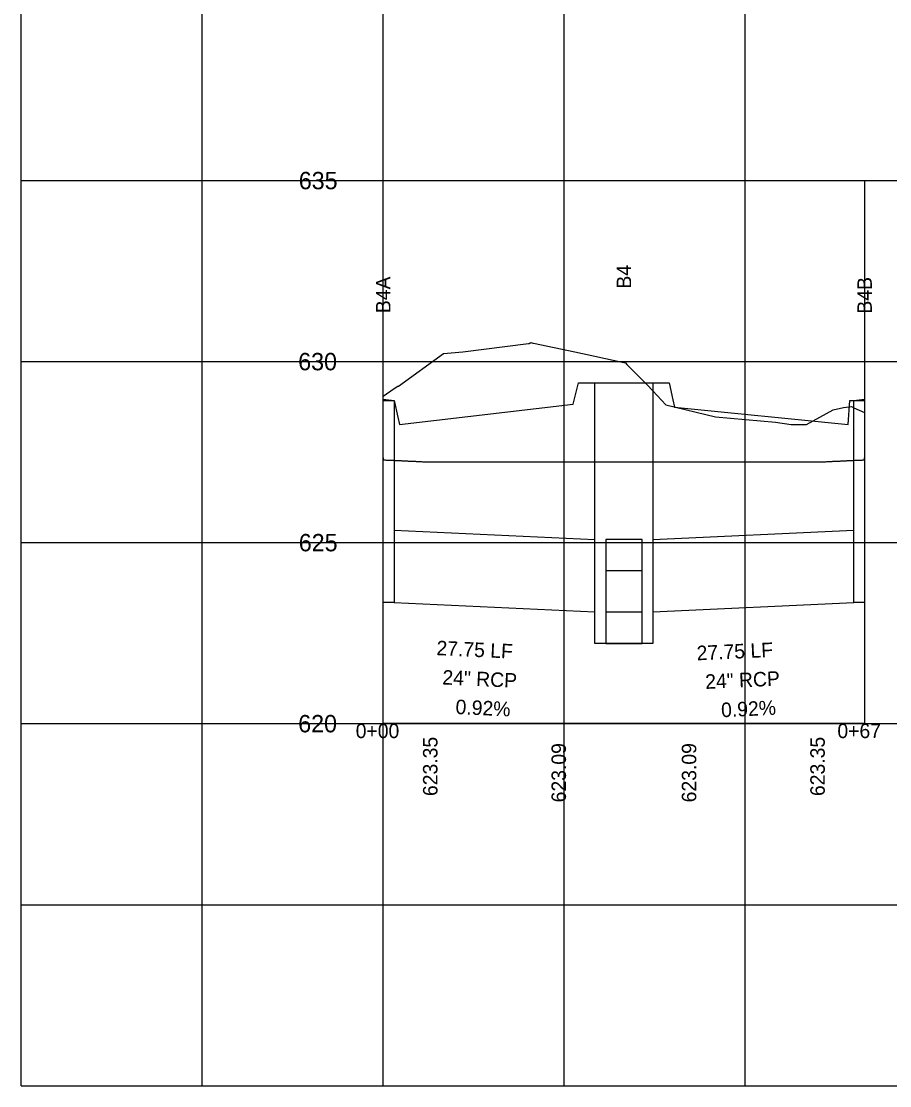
# Model space of a CAD drawing. Extents: x 2254979 to 2278074, y 13790855 to 13792793.
# Drawn here: x 2276749.4 to 2276869.4, y 13792492.6 to 13792639.6 of the extents above; entities that cross this region are included whole.
import ezdxf

# ---------------------------------------------------------------- set-up
doc = ezdxf.new("R2010")
doc.units = 0
for name, color, linetype in [('blank4', 7, 'Continuous'), ('BORD_grid_bottom_major_5int', 7, 'Continuous'), ('D_DRN_PROF_HGL', 7, 'Continuous'), ('D_PROF_1', 7, 'Continuous'), ('D_PROF_NOTES_1', 7, 'Continuous'), ('Default', 7, 'Continuous'), ('Drain_PipeInside', 7, 'Continuous'), ('E_Terrain', 7, 'Continuous'), ('Inlet', 7, 'Continuous'), ('z - Construction', 7, 'Continuous')]:
    doc.layers.add(name, color=color, linetype=linetype)

msp = doc.modelspace()

# ---------------------------------------------------------------- linework, layer by layer
at = {"layer": 'blank4'}
msp.add_lwpolyline([(2276799.4, 13792542.6), (2276799.4, 13792617.6), (2276865.9, 13792617.6), (2276865.9, 13792542.6)], close=True, dxfattribs=at)
at = {"layer": 'BORD_grid_bottom_major_5int'}
for p, q in [((2276749.4, 13792492.6), (2276749.4, 13792792.6)), ((2276774.4, 13792492.6), (2276774.4, 13792792.6)), ((2276799.4, 13792492.6), (2276799.4, 13792792.6)), ((2276824.4, 13792492.6), (2276824.4, 13792792.6)), ((2276849.4, 13792492.6), (2276849.4, 13792792.6)), ((2276749.4, 13792617.6), (2277074.4, 13792617.6)), ((2276749.4, 13792592.6), (2277074.4, 13792592.6)), ((2276749.4, 13792567.6), (2277074.4, 13792567.6)), ((2276749.4, 13792542.6), (2277074.4, 13792542.6)), ((2276749.4, 13792517.6), (2277074.4, 13792517.6)), ((2276749.4, 13792492.6), (2277074.4, 13792492.6))]:
    msp.add_line(p, q, dxfattribs=at)
at = {"layer": 'D_DRN_PROF_HGL'}
msp.add_line((2276832.65, 13792578.77), (2276832.65, 13792578.77), dxfattribs=at)
for points in [[(2276799.4, 13792579.32), (2276799.4, 13792579.03), (2276799.47, 13792579.03), (2276799.58, 13792579.02), (2276799.69, 13792579.02), (2276799.8, 13792579.01), (2276799.91, 13792579.01), (2276800.01, 13792579), (2276800.12, 13792579), (2276800.23, 13792578.99), (2276800.34, 13792578.99), (2276800.45, 13792578.98), (2276800.56, 13792578.98), (2276800.67, 13792578.97), (2276800.78, 13792578.97), (2276800.89, 13792578.96), (2276801, 13792578.96), (2276801.11, 13792578.95), (2276801.22, 13792578.95), (2276801.32, 13792578.94), (2276801.43, 13792578.94), (2276801.54, 13792578.93), (2276801.65, 13792578.93), (2276801.76, 13792578.92), (2276801.87, 13792578.92), (2276801.98, 13792578.91), (2276802.09, 13792578.91), (2276802.2, 13792578.9), (2276802.31, 13792578.9), (2276802.42, 13792578.89), (2276802.53, 13792578.89), (2276802.63, 13792578.88), (2276802.74, 13792578.88), (2276802.85, 13792578.87), (2276802.96, 13792578.87), (2276803.07, 13792578.86), (2276803.18, 13792578.86), (2276803.29, 13792578.85), (2276803.4, 13792578.85), (2276803.51, 13792578.84), (2276803.62, 13792578.84), (2276803.73, 13792578.83), (2276803.84, 13792578.83), (2276803.94, 13792578.82), (2276804.05, 13792578.82), (2276804.16, 13792578.81), (2276804.27, 13792578.81), (2276804.38, 13792578.8), (2276804.49, 13792578.8), (2276804.6, 13792578.79), (2276804.71, 13792578.79), (2276804.82, 13792578.78), (2276804.93, 13792578.78), (2276805.04, 13792578.78), (2276805.15, 13792578.78), (2276805.25, 13792578.78), (2276805.36, 13792578.78), (2276805.47, 13792578.78), (2276805.58, 13792578.78), (2276805.69, 13792578.78), (2276805.8, 13792578.78), (2276805.91, 13792578.78), (2276806.02, 13792578.78), (2276806.13, 13792578.78), (2276806.24, 13792578.78), (2276806.35, 13792578.78), (2276806.46, 13792578.78), (2276806.56, 13792578.78), (2276806.67, 13792578.78), (2276806.78, 13792578.78), (2276806.89, 13792578.78), (2276807, 13792578.78), (2276807.11, 13792578.78), (2276807.22, 13792578.77), (2276807.33, 13792578.77), (2276807.44, 13792578.77), (2276807.55, 13792578.77), (2276807.66, 13792578.77), (2276807.77, 13792578.77), (2276807.87, 13792578.77), (2276807.98, 13792578.77), (2276808.09, 13792578.77), (2276808.2, 13792578.77), (2276808.31, 13792578.77), (2276808.42, 13792578.77), (2276808.53, 13792578.77), (2276808.64, 13792578.77), (2276808.75, 13792578.77), (2276808.86, 13792578.77), (2276808.97, 13792578.77), (2276809.08, 13792578.77), (2276809.18, 13792578.77), (2276809.29, 13792578.77), (2276809.4, 13792578.77), (2276809.51, 13792578.77), (2276809.62, 13792578.77), (2276809.73, 13792578.77), (2276809.84, 13792578.77), (2276809.95, 13792578.77), (2276810.06, 13792578.77), (2276810.17, 13792578.77), (2276810.28, 13792578.77), (2276810.39, 13792578.77), (2276810.49, 13792578.77), (2276810.6, 13792578.77), (2276810.71, 13792578.77), (2276810.82, 13792578.77), (2276810.93, 13792578.77), (2276811.04, 13792578.77), (2276811.15, 13792578.77), (2276811.26, 13792578.77), (2276811.37, 13792578.77), (2276811.48, 13792578.77), (2276811.59, 13792578.77), (2276811.7, 13792578.77), (2276811.8, 13792578.77), (2276811.91, 13792578.77), (2276812.02, 13792578.77), (2276812.13, 13792578.77), (2276812.24, 13792578.77), (2276812.35, 13792578.77), (2276812.46, 13792578.77), (2276812.57, 13792578.77), (2276812.68, 13792578.77), (2276812.79, 13792578.77), (2276812.9, 13792578.77), (2276813, 13792578.77), (2276813.11, 13792578.77), (2276813.22, 13792578.77), (2276813.33, 13792578.77), (2276813.44, 13792578.77), (2276813.55, 13792578.77), (2276813.66, 13792578.77), (2276813.77, 13792578.77), (2276813.88, 13792578.77), (2276813.99, 13792578.77), (2276814.1, 13792578.77), (2276814.21, 13792578.77), (2276814.31, 13792578.77), (2276814.42, 13792578.77), (2276814.53, 13792578.77), (2276814.64, 13792578.77), (2276814.75, 13792578.77), (2276814.86, 13792578.77), (2276814.97, 13792578.77), (2276815.08, 13792578.77), (2276815.19, 13792578.77), (2276815.3, 13792578.77), (2276815.41, 13792578.77), (2276815.52, 13792578.77), (2276815.62, 13792578.77), (2276815.73, 13792578.77), (2276815.84, 13792578.77), (2276815.95, 13792578.77), (2276816.06, 13792578.77), (2276816.17, 13792578.77), (2276816.28, 13792578.77), (2276816.39, 13792578.77), (2276816.5, 13792578.77), (2276816.61, 13792578.77), (2276816.72, 13792578.77), (2276816.83, 13792578.77), (2276816.93, 13792578.77), (2276817.04, 13792578.77), (2276817.15, 13792578.77), (2276817.26, 13792578.77), (2276817.37, 13792578.77), (2276817.48, 13792578.77), (2276817.59, 13792578.77), (2276817.7, 13792578.77), (2276817.81, 13792578.77), (2276817.92, 13792578.77), (2276818.03, 13792578.77), (2276818.14, 13792578.77), (2276818.24, 13792578.77), (2276818.35, 13792578.77), (2276818.46, 13792578.77), (2276818.57, 13792578.77), (2276818.68, 13792578.77), (2276818.79, 13792578.77), (2276818.9, 13792578.77), (2276819.01, 13792578.77), (2276819.12, 13792578.77), (2276819.23, 13792578.77), (2276819.34, 13792578.77), (2276819.45, 13792578.77), (2276819.55, 13792578.77), (2276819.66, 13792578.77), (2276819.77, 13792578.77), (2276819.88, 13792578.77), (2276819.99, 13792578.77), (2276820.1, 13792578.77), (2276820.21, 13792578.77), (2276820.32, 13792578.77), (2276820.43, 13792578.77), (2276820.54, 13792578.77), (2276820.65, 13792578.77), (2276820.76, 13792578.77), (2276820.86, 13792578.77), (2276820.97, 13792578.77), (2276821.08, 13792578.77), (2276821.19, 13792578.77), (2276821.3, 13792578.77), (2276821.41, 13792578.77), (2276821.52, 13792578.77), (2276821.63, 13792578.77), (2276821.74, 13792578.77), (2276821.85, 13792578.77), (2276821.96, 13792578.77), (2276822.07, 13792578.77), (2276822.17, 13792578.77), (2276822.28, 13792578.77), (2276822.39, 13792578.77), (2276822.5, 13792578.77), (2276822.61, 13792578.77), (2276822.72, 13792578.77), (2276822.83, 13792578.77), (2276822.94, 13792578.77), (2276823.05, 13792578.77), (2276823.16, 13792578.77), (2276823.27, 13792578.77), (2276823.38, 13792578.77), (2276823.48, 13792578.77), (2276823.59, 13792578.77), (2276823.7, 13792578.77), (2276823.81, 13792578.77), (2276823.92, 13792578.77), (2276824.03, 13792578.77), (2276824.14, 13792578.77), (2276824.25, 13792578.77), (2276824.36, 13792578.77), (2276824.47, 13792578.77), (2276824.58, 13792578.77), (2276824.69, 13792578.77), (2276824.79, 13792578.77), (2276824.9, 13792578.77), (2276825.01, 13792578.77), (2276825.12, 13792578.77), (2276825.23, 13792578.77), (2276825.34, 13792578.77), (2276825.45, 13792578.77), (2276825.56, 13792578.77), (2276825.67, 13792578.77), (2276825.78, 13792578.77), (2276825.89, 13792578.77), (2276826, 13792578.77), (2276826.1, 13792578.77), (2276826.21, 13792578.77), (2276826.32, 13792578.77), (2276826.43, 13792578.77), (2276826.54, 13792578.77), (2276826.65, 13792578.77), (2276826.76, 13792578.77), (2276826.87, 13792578.77), (2276826.98, 13792578.77), (2276827.09, 13792578.77), (2276827.2, 13792578.77), (2276827.31, 13792578.77), (2276827.41, 13792578.77), (2276827.52, 13792578.77), (2276827.63, 13792578.77), (2276827.74, 13792578.77), (2276827.85, 13792578.77), (2276827.96, 13792578.77), (2276828.07, 13792578.77), (2276828.18, 13792578.77), (2276828.29, 13792578.77), (2276828.4, 13792578.77), (2276828.51, 13792578.77), (2276828.62, 13792578.77), (2276828.72, 13792578.77), (2276828.83, 13792578.77), (2276828.94, 13792578.77), (2276829.05, 13792578.77), (2276829.16, 13792578.77), (2276829.27, 13792578.77), (2276829.38, 13792578.77), (2276829.49, 13792578.77), (2276829.6, 13792578.77), (2276829.71, 13792578.77), (2276829.82, 13792578.77), (2276829.93, 13792578.77), (2276830.03, 13792578.77), (2276830.14, 13792578.77), (2276830.25, 13792578.77), (2276830.36, 13792578.77), (2276830.47, 13792578.77), (2276830.58, 13792578.77), (2276830.69, 13792578.77), (2276830.8, 13792578.77), (2276830.91, 13792578.77), (2276831.02, 13792578.77), (2276831.13, 13792578.77), (2276831.24, 13792578.77), (2276831.34, 13792578.77), (2276831.45, 13792578.77), (2276831.56, 13792578.77), (2276831.67, 13792578.77), (2276831.78, 13792578.77), (2276831.89, 13792578.77), (2276832, 13792578.77), (2276832.11, 13792578.77), (2276832.22, 13792578.77), (2276832.33, 13792578.77), (2276832.44, 13792578.77), (2276832.55, 13792578.77), (2276832.65, 13792578.77)], [(2276832.65, 13792578.77), (2276832.76, 13792578.77), (2276832.87, 13792578.77), (2276832.98, 13792578.77), (2276833.09, 13792578.77), (2276833.2, 13792578.77), (2276833.31, 13792578.77), (2276833.42, 13792578.77), (2276833.53, 13792578.77), (2276833.63, 13792578.77), (2276833.74, 13792578.77), (2276833.85, 13792578.77), (2276833.96, 13792578.77), (2276834.07, 13792578.77), (2276834.18, 13792578.77), (2276834.29, 13792578.77), (2276834.4, 13792578.77), (2276834.51, 13792578.77), (2276834.62, 13792578.77), (2276834.72, 13792578.77), (2276834.83, 13792578.77), (2276834.94, 13792578.77), (2276835.05, 13792578.77), (2276835.16, 13792578.77), (2276835.27, 13792578.77), (2276835.38, 13792578.77), (2276835.49, 13792578.77), (2276835.6, 13792578.77), (2276835.71, 13792578.77), (2276835.81, 13792578.77), (2276835.92, 13792578.77), (2276836.03, 13792578.77), (2276836.14, 13792578.77), (2276836.25, 13792578.77), (2276836.36, 13792578.77), (2276836.47, 13792578.77), (2276836.58, 13792578.77), (2276836.69, 13792578.77), (2276836.79, 13792578.77), (2276836.9, 13792578.77), (2276837.01, 13792578.77), (2276837.12, 13792578.77), (2276837.23, 13792578.77), (2276837.34, 13792578.77), (2276837.45, 13792578.77), (2276837.56, 13792578.77), (2276837.67, 13792578.77), (2276837.78, 13792578.77), (2276837.88, 13792578.77), (2276837.99, 13792578.77), (2276838.1, 13792578.77), (2276838.21, 13792578.77), (2276838.32, 13792578.77), (2276838.43, 13792578.77), (2276838.54, 13792578.77), (2276838.65, 13792578.77), (2276838.76, 13792578.77), (2276838.86, 13792578.77), (2276838.97, 13792578.77), (2276839.08, 13792578.77), (2276839.19, 13792578.77), (2276839.3, 13792578.77), (2276839.41, 13792578.77), (2276839.52, 13792578.77), (2276839.63, 13792578.77), (2276839.74, 13792578.77), (2276839.85, 13792578.77), (2276839.95, 13792578.77), (2276840.06, 13792578.77), (2276840.17, 13792578.77), (2276840.28, 13792578.77), (2276840.39, 13792578.77), (2276840.5, 13792578.77), (2276840.61, 13792578.77), (2276840.72, 13792578.77), (2276840.83, 13792578.77), (2276840.93, 13792578.77), (2276841.04, 13792578.77), (2276841.15, 13792578.77), (2276841.26, 13792578.77), (2276841.37, 13792578.77), (2276841.48, 13792578.77), (2276841.59, 13792578.77), (2276841.7, 13792578.77), (2276841.81, 13792578.77), (2276841.92, 13792578.77), (2276842.02, 13792578.77), (2276842.13, 13792578.77), (2276842.24, 13792578.77), (2276842.35, 13792578.77), (2276842.46, 13792578.77), (2276842.57, 13792578.77), (2276842.68, 13792578.77), (2276842.79, 13792578.77), (2276842.9, 13792578.77), (2276843.01, 13792578.77), (2276843.11, 13792578.77), (2276843.22, 13792578.77), (2276843.33, 13792578.77), (2276843.44, 13792578.77), (2276843.55, 13792578.77), (2276843.66, 13792578.77), (2276843.77, 13792578.77), (2276843.88, 13792578.77), (2276843.99, 13792578.77), (2276844.09, 13792578.77), (2276844.2, 13792578.77), (2276844.31, 13792578.77), (2276844.42, 13792578.77), (2276844.53, 13792578.77), (2276844.64, 13792578.77), (2276844.75, 13792578.77), (2276844.86, 13792578.77), (2276844.97, 13792578.77), (2276845.08, 13792578.77), (2276845.18, 13792578.77), (2276845.29, 13792578.77), (2276845.4, 13792578.77), (2276845.51, 13792578.77), (2276845.62, 13792578.77), (2276845.73, 13792578.77), (2276845.84, 13792578.77), (2276845.95, 13792578.77), (2276846.06, 13792578.77), (2276846.16, 13792578.77), (2276846.27, 13792578.77), (2276846.38, 13792578.77), (2276846.49, 13792578.77), (2276846.6, 13792578.77), (2276846.71, 13792578.77), (2276846.82, 13792578.77), (2276846.93, 13792578.77), (2276847.04, 13792578.77), (2276847.15, 13792578.77), (2276847.25, 13792578.77), (2276847.36, 13792578.77), (2276847.47, 13792578.77), (2276847.58, 13792578.77), (2276847.69, 13792578.77), (2276847.8, 13792578.77), (2276847.91, 13792578.77), (2276848.02, 13792578.77), (2276848.13, 13792578.77), (2276848.23, 13792578.77), (2276848.34, 13792578.77), (2276848.45, 13792578.77), (2276848.56, 13792578.77), (2276848.67, 13792578.77), (2276848.78, 13792578.77), (2276848.89, 13792578.77), (2276849, 13792578.77), (2276849.11, 13792578.77), (2276849.22, 13792578.77), (2276849.32, 13792578.77), (2276849.43, 13792578.77), (2276849.54, 13792578.77), (2276849.65, 13792578.77), (2276849.76, 13792578.77), (2276849.87, 13792578.77), (2276849.98, 13792578.77), (2276850.09, 13792578.77), (2276850.2, 13792578.77), (2276850.31, 13792578.77), (2276850.41, 13792578.77), (2276850.52, 13792578.77), (2276850.63, 13792578.77), (2276850.74, 13792578.77), (2276850.85, 13792578.77), (2276850.96, 13792578.77), (2276851.07, 13792578.77), (2276851.18, 13792578.77), (2276851.29, 13792578.77), (2276851.39, 13792578.77), (2276851.5, 13792578.77), (2276851.61, 13792578.77), (2276851.72, 13792578.77), (2276851.83, 13792578.77), (2276851.94, 13792578.77), (2276852.05, 13792578.77), (2276852.16, 13792578.77), (2276852.27, 13792578.77), (2276852.38, 13792578.77), (2276852.48, 13792578.77), (2276852.59, 13792578.77), (2276852.7, 13792578.77), (2276852.81, 13792578.77), (2276852.92, 13792578.77), (2276853.03, 13792578.77), (2276853.14, 13792578.77), (2276853.25, 13792578.77), (2276853.36, 13792578.77), (2276853.46, 13792578.77), (2276853.57, 13792578.77), (2276853.68, 13792578.77), (2276853.79, 13792578.77), (2276853.9, 13792578.77), (2276854.01, 13792578.77), (2276854.12, 13792578.77), (2276854.23, 13792578.77), (2276854.34, 13792578.77), (2276854.45, 13792578.77), (2276854.55, 13792578.77), (2276854.66, 13792578.77), (2276854.77, 13792578.77), (2276854.88, 13792578.77), (2276854.99, 13792578.77), (2276855.1, 13792578.77), (2276855.21, 13792578.77), (2276855.32, 13792578.77), (2276855.43, 13792578.77), (2276855.53, 13792578.77), (2276855.64, 13792578.77), (2276855.75, 13792578.77), (2276855.86, 13792578.77), (2276855.97, 13792578.77), (2276856.08, 13792578.77), (2276856.19, 13792578.77), (2276856.3, 13792578.77), (2276856.41, 13792578.77), (2276856.52, 13792578.77), (2276856.62, 13792578.77), (2276856.73, 13792578.77), (2276856.84, 13792578.77), (2276856.95, 13792578.77), (2276857.06, 13792578.77), (2276857.17, 13792578.77), (2276857.28, 13792578.77), (2276857.39, 13792578.77), (2276857.5, 13792578.77), (2276857.61, 13792578.77), (2276857.71, 13792578.77), (2276857.82, 13792578.77), (2276857.93, 13792578.77), (2276858.04, 13792578.77), (2276858.15, 13792578.77), (2276858.26, 13792578.77), (2276858.37, 13792578.77), (2276858.48, 13792578.77), (2276858.59, 13792578.77), (2276858.69, 13792578.77), (2276858.8, 13792578.77), (2276858.91, 13792578.77), (2276859.02, 13792578.77), (2276859.13, 13792578.77), (2276859.24, 13792578.77), (2276859.35, 13792578.77), (2276859.46, 13792578.77), (2276859.57, 13792578.77), (2276859.68, 13792578.77), (2276859.78, 13792578.77), (2276859.89, 13792578.77), (2276860, 13792578.77), (2276860.11, 13792578.77), (2276860.22, 13792578.77), (2276860.33, 13792578.77), (2276860.44, 13792578.77), (2276860.55, 13792578.78), (2276860.66, 13792578.79), (2276860.76, 13792578.79), (2276860.87, 13792578.8), (2276860.98, 13792578.8), (2276861.09, 13792578.81), (2276861.2, 13792578.81), (2276861.31, 13792578.82), (2276861.42, 13792578.82), (2276861.53, 13792578.83), (2276861.64, 13792578.83), (2276861.75, 13792578.84), (2276861.85, 13792578.84), (2276861.96, 13792578.85), (2276862.07, 13792578.85), (2276862.18, 13792578.86), (2276862.29, 13792578.86), (2276862.4, 13792578.87), (2276862.51, 13792578.87), (2276862.62, 13792578.88), (2276862.73, 13792578.88), (2276862.83, 13792578.89), (2276862.94, 13792578.89), (2276863.05, 13792578.9), (2276863.16, 13792578.9), (2276863.27, 13792578.91), (2276863.38, 13792578.91), (2276863.49, 13792578.92), (2276863.6, 13792578.92), (2276863.71, 13792578.93), (2276863.82, 13792578.93), (2276863.92, 13792578.94), (2276864.03, 13792578.94), (2276864.14, 13792578.95), (2276864.25, 13792578.95), (2276864.36, 13792578.96), (2276864.47, 13792578.96), (2276864.58, 13792578.97), (2276864.69, 13792578.97), (2276864.8, 13792578.98), (2276864.91, 13792578.98), (2276865.01, 13792578.99), (2276865.12, 13792578.99), (2276865.23, 13792579), (2276865.34, 13792579), (2276865.45, 13792579.01), (2276865.56, 13792579.01), (2276865.67, 13792579.02), (2276865.78, 13792579.02), (2276865.89, 13792579.03), (2276865.9, 13792579.02), (2276865.9, 13792579.31)]]:
    msp.add_lwpolyline(points, dxfattribs=at)
at = {"layer": 'D_PROF_1'}
msp.add_lwpolyline([(2276799.4, 13792587.4), (2276800.9, 13792587.25), (2276800.9, 13792587.25), (2276801.43, 13792584.94), (2276801.65, 13792583.92), (2276825.65, 13792586.74), (2276825.88, 13792587.63), (2276826.4, 13792589.65), (2276828.65, 13792589.65), (2276828.65, 13792589.65), (2276832.65, 13792589.65), (2276832.65, 13792589.65), (2276836.65, 13792589.65), (2276836.65, 13792589.65), (2276838.9, 13792589.65), (2276839.43, 13792587.34), (2276839.65, 13792586.32), (2276863.65, 13792583.92), (2276863.88, 13792587.25), (2276864.4, 13792587.25), (2276864.4, 13792587.25), (2276865.9, 13792587.4)], dxfattribs=at)
at = {"layer": 'Drain_PipeInside'}
for p, q in [((2276800.9, 13792569.33), (2276828.65, 13792568.05)), ((2276836.65, 13792568.05), (2276864.4, 13792569.33)), ((2276800.9, 13792559.33), (2276828.65, 13792558.05)), ((2276836.65, 13792558.05), (2276864.4, 13792559.33))]:
    msp.add_line(p, q, dxfattribs=at)
for points in [[(2276830.15, 13792558.05), (2276835.15, 13792558.05), (2276835.15, 13792568.05), (2276830.15, 13792568.05)], [(2276830.15, 13792553.69), (2276835.15, 13792553.69), (2276835.15, 13792563.69), (2276830.15, 13792563.69)]]:
    msp.add_lwpolyline(points, close=True, dxfattribs=at)
at = {"layer": 'E_Terrain'}
msp.add_lwpolyline([(2276799.4, 13792587.84), (2276799.41, 13792587.84), (2276800.9, 13792588.87), (2276800.9, 13792588.87), (2276801.43, 13792589.22), (2276801.53, 13792589.19), (2276807.71, 13792593.7), (2276810.42, 13792593.93), (2276819.47, 13792595.12), (2276819.55, 13792595.11), (2276819.81, 13792595.23), (2276820.08, 13792595.15), (2276820.14, 13792595.15), (2276825.86, 13792593.94), (2276828.65, 13792593.33), (2276828.65, 13792593.33), (2276832.65, 13792592.46), (2276832.65, 13792592.46), (2276832.87, 13792592.41), (2276833.04, 13792592.22), (2276835.92, 13792589.35), (2276836.65, 13792588.55), (2276836.65, 13792588.55), (2276838.43, 13792586.63), (2276845.3, 13792584.95), (2276853.59, 13792584.22), (2276855.74, 13792583.9), (2276857.87, 13792583.91), (2276861.56, 13792585.95), (2276862.98, 13792586.25), (2276864.08, 13792586.38), (2276864.4, 13792586.23), (2276864.4, 13792586.23), (2276865.9, 13792585.57)], dxfattribs=at)
at = {"layer": 'Inlet'}
for points in [[(2276828.65, 13792589.65), (2276836.65, 13792589.65), (2276836.65, 13792553.69), (2276828.65, 13792553.69)], [(2276799.4, 13792587.25), (2276800.9, 13792587.25), (2276800.9, 13792559.33), (2276799.4, 13792559.33)], [(2276864.4, 13792587.25), (2276865.9, 13792587.25), (2276865.9, 13792559.33), (2276864.4, 13792559.33)]]:
    msp.add_lwpolyline(points, close=True, dxfattribs=at)
at = {"layer": 'z - Construction'}
for p, q in [((2276799.4, 13792592.6), (2276865.9, 13792592.6)), ((2276799.4, 13792567.6), (2276865.9, 13792567.6))]:
    msp.add_line(p, q, dxfattribs=at)

# ---------------------------------------------------------------- texts
at = {"layer": 'D_PROF_NOTES_1'}
for s, rotation, p in [('B4', 90, (2276833.65, 13792602.68)), ('B4A', 90, (2276800.4, 13792599.29)), ('B4B', 90, (2276866.9, 13792599.23)), ('27.75 LF', 357.359, (2276806.72, 13792552.07)), ('27.75 LF', 2.641, (2276842.74, 13792551.34)), ('24" RCP', 357.359, (2276807.54, 13792548.02)), ('24" RCP', 2.641, (2276843.93, 13792547.39)), ('0.92%', 357.359, (2276809.36, 13792543.94)), ('0.92%', 2.641, (2276846.12, 13792543.48)), ('623.35', 90, (2276806.9, 13792532.6)), ('623.09', 90, (2276824.65, 13792531.73)), ('623.09', 90, (2276842.65, 13792531.73)), ('623.35', 90, (2276860.4, 13792532.6))]:
    msp.add_text(s, height=2, rotation=rotation, dxfattribs=at).set_placement(p)
at = {"layer": 'Default'}
for s, height, p in [('635', 2.4, (2276787.74, 13792616.4)), ('630', 2.4, (2276787.66, 13792591.4)), ('625', 2.4, (2276787.74, 13792566.4)), ('620', 2.4, (2276787.66, 13792541.4)), ('0+00', 2, (2276795.6, 13792540.6)), ('0+67', 2, (2276862.14, 13792540.6))]:
    msp.add_text(s, height=height, dxfattribs=at).set_placement(p)

doc.saveas('drawing.dxf')
